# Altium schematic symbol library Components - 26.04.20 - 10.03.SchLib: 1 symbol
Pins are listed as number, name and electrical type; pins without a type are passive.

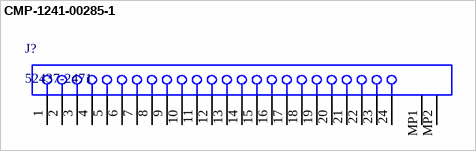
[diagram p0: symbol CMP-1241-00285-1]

## CMP-1241-00285-1
designator J?, comment 52437-2471
0.5 mm Pitch Easy-On(TM) Type FPC Connector, Right Angle, ZIF, SMT, Bottom Contact, 24 Circuits, -40 to 85 degC, ELV and RoHS Compliant, Tape and Reel; Manufacturer: Molex; Material - Metal: Phosphor Bronze; Material - Plating Mating: Gold; Durability (mating cycles max): 20; Stackable: No; Entry Angle: 90degrees Angle; Circuits (Loaded): 24; Current (Max per Contact): 0.5A; PCB Retention: None; Pitch - Mating Interface: 0.50mm; Polarized to PCB: Yes; Voltage (Max): 50V
footprint MOLX-52437-2471 (FPC Connector, 24-Leads, Right Angle, Pitch 0.5 mm, SMT)
pins: 1, 2, 3, 4, 5, 6, 7, 8, 9, 10, 11, 12, 13, 14, 15, 16, 17, 18, 19, 20, 21, 22, 23, 24, MP1, MP2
